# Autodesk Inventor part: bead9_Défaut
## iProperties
Shininess: 64.0
Length Units: 11269
Angle Units: 11279
Time Units: 11290
Mass Units: 11283
Length Display Precision: 3
Angle Display Precision: 2
Compacted: True
Part Number: bead9_Défaut
Document SubType Name: Modeling
Created: 2006-01
Material: Par défaut
Designer: Fricot
Density: 0.0
Volumn: 0.0
Area: 0.0
PropertySet Name: Model Information
Control State: 0
Master: False
Checked Out: False
Author: Fricot
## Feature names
1. Base1
